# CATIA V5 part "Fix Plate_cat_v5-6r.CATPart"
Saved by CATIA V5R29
Part number: Fix Plate
Bounding box of the stored display mesh (mm): x -45 to 45, y -150 to 150, z -40 to 230
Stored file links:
  C:\Users\CADCIM 00\Desktop\New folder (2)\c16\New folder\Slide Curve\Fix Plate_cat_v5-6r.CATPart
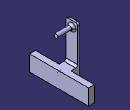
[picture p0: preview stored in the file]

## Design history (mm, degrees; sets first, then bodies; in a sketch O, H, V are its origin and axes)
Body1 (main body)
  Sketch1 on yz-plane, origin (0, 0, 0), H (0, 1, 0), V (0, 0, 1)
    line L1 (150, 40) -> (150, -40)
    line L2 (150, -40) -> (-150, -40)
    line L3 (-150, -40) -> (-150, 40)
    line L4 (-150, 40) -> (150, 40)
    length L4 = 300
    length L1 = 80
    vertical: L1 V, L3 V
    horizontal: L2 H, L4 H
    equidistance: L1 L3 O, L2 L4 O
  Pad1: profile Sketch1, direction (1, 0, 0), length 30
  Point1: type OnCurve, Support edge [face of Pad1 from Sketch1.L4 | end face of Pad1], Ratio 0.5
  Sketch2 on start face of Pad1, origin (0, 0, 0), H (0, -1, 0), V (0, 0, 1)
    circle A1 centre (0, 200) radius 10
    point P1 (0, 200)
    reference projected line E1 (-150, 40) -> (150, 40) from edge [start face of Pad1 | face of Pad1 from Sketch1.L4]
    radius A1 = 10
    distance E1 P1 = 160
    coincidence: P1 V
  Pad2: profile Sketch2, direction (1, 0, 0), length 45, mirrored extent
  Sketch3 on start face of Pad2, origin (-45, 0, 0), H (0, -1, 0), V (0, 0, 1)
    line L1 (30, -40) -> (-30, -40)
    line L2 (-30, -40) -> (-30, 230)
    line L3 (-30, 230) -> (30, 230)
    line L4 (30, 230) -> (30, -40)
    reference projected line E1 (-150, 40) -> (150, 40) from edge [start face of Pad1 | face of Pad1 from Sketch1.L4]
    length L3 = 60
    distance V L2 = 30
    distance E1 L3 = 190
    horizontal: L1 H, L3 H
    vertical: L2 V, L4 V
  Pad3: profile Sketch3, direction (1, 0, 0), length 10
  Sketch4 on end face of Pad3, origin (-35, 0, 0), H (0, 1, 0), V (0, 0, 1)
    line L1 (-30, 40) -> (30, 40)
    line L2 (30, 40) -> (30, -40)
    line L3 (30, -40) -> (-30, -40)
    line L4 (-30, -40) -> (-30, 40)
    reference projected line E1 (150, 40) -> (-150, 40) from edge [face of Pad1 from Sketch1.L4 | end face of Pad1]
    reference projected line E2 (-30, -40) -> (-30, 230) from edge [end face of Pad3 | face of Pad3 from Sketch3.L4]
    reference projected line E3 (-150, -40) -> (150, -40) from edge [face of Pad1 from Sketch1.L2 | end face of Pad1]
    reference projected line E4 (30, 230) -> (30, -40) from edge [end face of Pad3 | face of Pad3 from Sketch3.L2]
    horizontal: L1 H, L3 H
    vertical: L2 V, L4 V
    coincidence: L1 E1, L4 E2, L3 E3, L2 E4
  Pad4: profile Sketch4, direction (1, 0, 0), up to the existing solid (limit type 2)
  Fillet1: radius 10, on edge [face of Pad3 from Sketch3.L3 | face of Pad3]; edge [face of Pad2 from Sketch2.A1 | end face of Pad3]; edge [face of Pad4 | face of Pad3 from Sketch3.L3]; edge [end face of Pad3 | face of Pad1]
